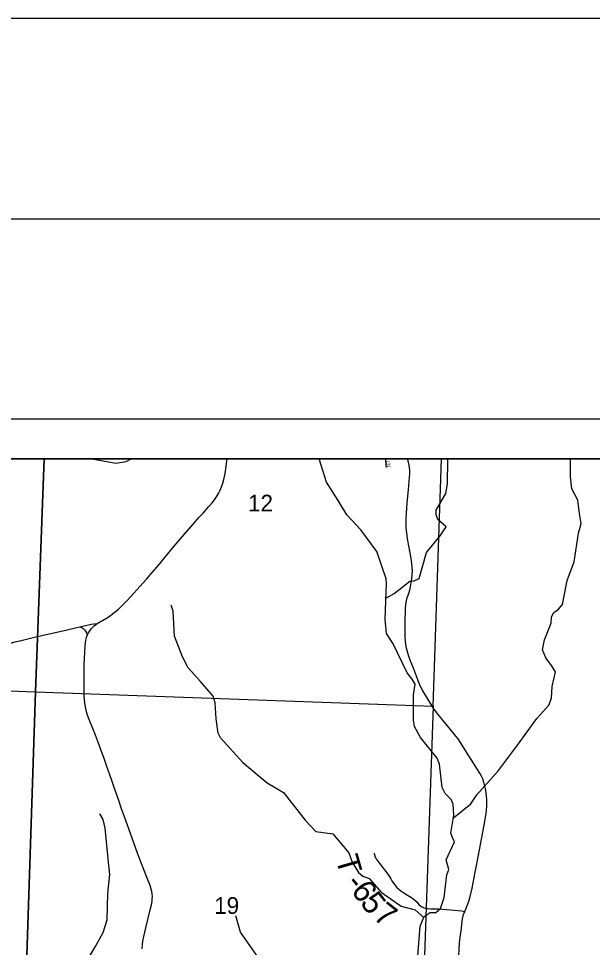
# Model space of a CAD drawing. Extents: x 0 to 34, y 0 to 22.
# Drawn here: x 26.701 to 28.135, y 19.68 to 22 of the extents above; entities that cross this region are included whole.
import ezdxf

# ---------------------------------------------------------------- set-up
doc = ezdxf.new("R2010")
doc.units = 0
for name, color, linetype in [('GM_X_Adjacent_County', 7, 'Continuous'), ('GM_X_County', 7, 'Continuous'), ('GM_X_County_Road', 7, 'Continuous'), ('GM_X_Minor_River', 7, 'Continuous'), ('GM_X_Section', 7, 'Continuous'), ('GM_X_Section_Text', 7, 'Continuous'), ('GM_X_State_Route', 7, 'Continuous'), ('GM_X_Township', 7, 'Continuous'), ('GM_X_Township_Road', 7, 'Continuous'), ('GM_X_Township_Road_Text', 7, 'Continuous'), ('GM_X_Township_Subdivision', 7, 'Continuous'), ('GM_X_Township_Subdivision_Text', 7, 'Continuous'), ('SH_Border', 7, 'Continuous'), ('SH_Cut_Line', 7, 'Continuous'), ('SH_Data', 7, 'Continuous')]:
    doc.layers.add(name, color=color, linetype=linetype)

msp = doc.modelspace()

# ---------------------------------------------------------------- linework, layer by layer
at = {"layer": 'GM_X_Adjacent_County'}
msp.add_lwpolyline([(28.7526, 20.9), (24.0167, 20.9), (24.0167, 14.1), (28.5181, 14.1)], dxfattribs=at)
at = {"layer": 'GM_X_County'}
msp.add_lwpolyline([(28.7526, 20.9), (24.0167, 20.9), (24.0167, 14.1), (28.5181, 14.1)], dxfattribs=at)
at = {"layer": 'GM_X_County_Road'}
for points in [[(27.8159, 19.7694), (27.8228, 19.7858), (27.8267, 19.7976), (27.8292, 19.8065), (27.8341, 19.8277), (27.842, 19.8673), (27.8471, 19.8926), (27.8647, 19.9854), (27.8693, 20.014), (27.8703, 20.0215), (27.8711, 20.0331), (27.8713, 20.0416), (27.8714, 20.0488), (27.8706, 20.0571), (27.8682, 20.0725), (27.8655, 20.0855), (27.8636, 20.0927), (27.8609, 20.1008), (27.8577, 20.1076), (27.8536, 20.1149), (27.8463, 20.1269), (27.8379, 20.1399), (27.8258, 20.158), (27.7991, 20.2006), (27.794, 20.2074), (27.788, 20.2148), (27.7495, 20.2613), (27.7387, 20.2759), (27.7336, 20.2842), (27.7247, 20.2988), (27.7177, 20.3101), (27.7101, 20.322), (27.7061, 20.3295), (27.7026, 20.3374), (27.6996, 20.3452), (27.6954, 20.3569), (27.6875, 20.3772), (27.6796, 20.3974), (27.6745, 20.4121), (27.6719, 20.421), (27.6705, 20.427), (27.6689, 20.4362), (27.6678, 20.4455), (27.6672, 20.4548), (27.667, 20.4703), (27.6671, 20.492), (27.6679, 20.5262), (27.6686, 20.5355), (27.6695, 20.5416), (27.6715, 20.5507), (27.6742, 20.5596), (27.6788, 20.572), (27.6807, 20.5803), (27.6824, 20.5901), (27.6837, 20.6003), (27.6848, 20.6111), (27.6851, 20.6205), (27.6848, 20.6297), (27.6839, 20.639), (27.682, 20.6513), (27.677, 20.6787), (27.6732, 20.7), (27.6709, 20.7153), (27.6697, 20.7277), (27.6692, 20.737), (27.6692, 20.7431), (27.6694, 20.7493), (27.6702, 20.7648), (27.6724, 20.7894), (27.6755, 20.8233), (27.6791, 20.8632), (27.6788, 20.8721), (27.6772, 20.884), (27.6745, 20.8948), (27.6732, 20.9)], [(26.5789, 20.4155), (26.5932, 20.4188), (26.6296, 20.4271), (26.6717, 20.4376), (26.6929, 20.4428), (26.711, 20.4472), (26.7411, 20.4544), (26.7593, 20.4586), (26.8229, 20.4731), (26.8471, 20.4786), (26.8546, 20.4804)], [(26.8546, 20.4804), (26.8682, 20.4835), (26.883, 20.4869), (26.8901, 20.4882), (26.8977, 20.4888)], [(26.8546, 20.4804), (26.8577, 20.4793), (26.8604, 20.4778), (26.8626, 20.4763), (26.8644, 20.4749), (26.8664, 20.473), (26.8687, 20.4698), (26.8707, 20.4659), (26.8727, 20.4587)], [(27.8003, 19.6426), (27.8026, 19.6909), (27.8045, 19.7047), (27.808, 19.727), (27.8088, 19.7389), (27.8107, 19.751), (27.8132, 19.7616), (27.8159, 19.7694)]]:
    msp.add_lwpolyline(points, dxfattribs=at)
at = {"layer": 'GM_X_Minor_River'}
for points in [[(26.8844, 20.9), (26.885, 20.8998), (26.9445, 20.8896), (26.9703, 20.8935), (26.9827, 20.9)], [(27.7597, 20.0795), (27.753, 20.1378), (27.7472, 20.1522), (27.705, 20.204), (27.6904, 20.2312), (27.6875, 20.2478), (27.688, 20.3108), (27.6923, 20.3373), (27.6849, 20.3498), (27.6723, 20.3656), (27.6367, 20.438), (27.6202, 20.4636), (27.6168, 20.4999), (27.6203, 20.5891), (27.6198, 20.6004), (27.5964, 20.6688), (27.5565, 20.7226), (27.5213, 20.7605), (27.5001, 20.7959), (27.4705, 20.8423), (27.4522, 20.9)], [(27.6189, 20.552), (27.6395, 20.5635), (27.6789, 20.595), (27.6899, 20.5955), (27.7019, 20.6013), (27.7205, 20.666), (27.7549, 20.7081), (27.7698, 20.7306), (27.7488, 20.7486), (27.7449, 20.7599), (27.7447, 20.7717), (27.7685, 20.8133), (27.7732, 20.8379), (27.774, 20.8982), (27.7744, 20.9)], [(27.7877, 20.0034), (27.8312, 20.0386), (27.8465, 20.0611), (27.9003, 20.122), (27.9477, 20.1847), (27.9958, 20.2515), (28.0257, 20.2852), (28.0327, 20.302), (28.0343, 20.3312), (28.0422, 20.368), (28.033, 20.3839), (28.0188, 20.4034), (28.0102, 20.4231), (28.0149, 20.4481), (28.0318, 20.49), (28.0328, 20.5056), (28.0384, 20.5166), (28.05, 20.5243), (28.0601, 20.5362), (28.0701, 20.5883), (28.0723, 20.5989), (28.0892, 20.6427), (28.1002, 20.7148), (28.1071, 20.7384), (28.1023, 20.7638), (28.0982, 20.7971), (28.0835, 20.8254), (28.0798, 20.8549), (28.0804, 20.9)], [(27.2617, 20.1419), (27.2061, 20.2034), (27.2003, 20.2147), (27.1948, 20.2503), (27.1927, 20.2909), (27.1873, 20.3072), (27.156, 20.3438), (27.1247, 20.3785), (27.1109, 20.4057), (27.091, 20.4576), (27.0872, 20.5194), (27.0829, 20.5345)], [(27.2617, 20.1419), (27.3226, 20.0907), (27.363, 20.0665), (27.4171, 19.9973), (27.4439, 19.9696), (27.4863, 19.9636), (27.5265, 19.9162), (27.5343, 19.8928), (27.5505, 19.8672), (27.5612, 19.8575), (27.5768, 19.8516), (27.607, 19.8174), (27.6569, 19.7827), (27.6918, 19.7736), (27.7138, 19.7548)], [(27.6991, 19.6576), (27.7044, 19.7331), (27.7147, 19.7568), (27.7293, 19.7671), (27.7433, 19.7673), (27.755, 19.7765), (27.7641, 19.8043), (27.7711, 19.8612), (27.7759, 19.8746), (27.7699, 19.8988), (27.7899, 19.9433), (27.7852, 19.9543), (27.7813, 19.9649), (27.7888, 20.0101), (27.7866, 20.0377), (27.7816, 20.049), (27.767, 20.0644), (27.7597, 20.0795)], [(26.7483, 19.5359), (26.7793, 19.5451), (26.8087, 19.5624), (26.849, 19.6062), (26.8941, 19.6835), (26.9124, 19.7169), (26.9225, 19.7489), (26.924, 19.8141), (26.9291, 19.8619), (26.9254, 19.9006), (26.9174, 19.9779), (26.9124, 19.9991), (26.904, 20.0135)], [(27.302, 19.6509), (27.2557, 19.7178), (27.2438, 19.7587)]]:
    msp.add_lwpolyline(points, dxfattribs=at)
at = {"layer": 'GM_X_Section'}
for p, q in [((26.7655, 20.9), (25.7754, 20.9)), ((27.7581, 20.9), (26.7655, 20.9))]:
    msp.add_line(p, q, dxfattribs=at)
for points in [[(25.7754, 20.9), (25.7533, 20.3558), (26.7437, 20.3179), (26.7655, 20.9)], [(26.7655, 20.9), (26.7437, 20.3179), (27.7374, 20.2821), (27.7581, 20.9)]]:
    msp.add_lwpolyline(points, dxfattribs=at)
for points in [[(25.7533, 20.3558), (26.7437, 20.3179), (26.7101, 19.3051), (25.7174, 19.3453)], [(26.7437, 20.3179), (27.7374, 20.2821), (27.7021, 19.2764), (26.7101, 19.3051)]]:
    msp.add_lwpolyline(points, close=True, dxfattribs=at)
at = {"layer": 'GM_X_State_Route'}
msp.add_lwpolyline([(27.0102, 19.6764), (27.0109, 19.6857), (27.0122, 19.695), (27.0145, 19.7072), (27.0194, 19.7285), (27.0252, 19.7526), (27.0304, 19.7738), (27.0331, 19.7858), (27.0347, 19.7949), (27.0354, 19.801), (27.0356, 19.8072), (27.0353, 19.8133), (27.0343, 19.8193), (27.0328, 19.8252), (27.0298, 19.834), (27.0207, 19.8571), (27.0151, 19.8716), (27.0051, 19.8976), (27.0017, 19.9063), (26.9974, 19.9179), (26.9901, 19.9383), (26.9807, 19.9646), (26.9662, 20.0056), (26.9587, 20.026), (26.9516, 20.0465), (26.9404, 20.0788), (26.9333, 20.0993), (26.9211, 20.1345), (26.9158, 20.149), (26.9054, 20.1782), (26.9011, 20.1899), (26.8935, 20.2102), (26.8855, 20.2304), (26.8794, 20.2447), (26.8761, 20.2534), (26.8731, 20.2622), (26.8705, 20.2712), (26.8684, 20.2804), (26.8668, 20.2896), (26.8658, 20.2989), (26.8654, 20.3083), (26.8652, 20.3269), (26.8655, 20.3518), (26.8655, 20.3641), (26.8656, 20.3857), (26.866, 20.4011), (26.8665, 20.4166), (26.8676, 20.4321), (26.8686, 20.4414), (26.8696, 20.4476), (26.871, 20.4537), (26.8719, 20.4567), (26.8727, 20.4587), (26.8735, 20.4605), (26.8758, 20.4653), (26.8791, 20.4706), (26.881, 20.4731), (26.883, 20.4755), (26.8852, 20.4778), (26.8864, 20.4789), (26.8905, 20.4828), (26.8977, 20.4888), (26.9074, 20.4944), (26.9107, 20.4964), (26.9207, 20.5021), (26.9298, 20.508), (26.9362, 20.513), (26.9436, 20.5188), (26.9507, 20.5249), (26.9621, 20.5355), (26.9729, 20.5466), (26.9897, 20.5649), (27.0043, 20.581), (27.0207, 20.5997), (27.035, 20.6161), (27.0531, 20.6374), (27.0631, 20.6493), (27.0847, 20.6758), (27.1149, 20.7112), (27.1373, 20.737), (27.1517, 20.7533), (27.1621, 20.7648), (27.1765, 20.781), (27.1846, 20.7904), (27.1904, 20.7978), (27.1958, 20.8054), (27.2006, 20.8135), (27.2049, 20.8218), (27.2085, 20.8305), (27.2115, 20.8394), (27.2139, 20.8484), (27.2172, 20.8637), (27.2202, 20.8821), (27.2225, 20.9)], dxfattribs=at)
at = {"layer": 'GM_X_Township'}
msp.add_lwpolyline([(28.7526, 20.9), (24.0167, 20.9), (24.0167, 18.4402)], dxfattribs=at)
at = {"layer": 'GM_X_Township_Road'}
msp.add_lwpolyline([(27.5895, 19.9148), (27.5917, 19.9075), (27.5925, 19.9052), (27.5937, 19.9028), (27.5955, 19.8996), (27.5985, 19.8955), (27.6039, 19.8881), (27.6122, 19.8775), (27.6187, 19.8692), (27.6255, 19.8602), (27.629, 19.8551), (27.6315, 19.8509), (27.6341, 19.8462), (27.6374, 19.8409), (27.6419, 19.8352), (27.6457, 19.8305), (27.6509, 19.8248), (27.6561, 19.821), (27.6635, 19.816), (27.6727, 19.8106), (27.6829, 19.8044), (27.69, 19.7989), (27.6967, 19.7928), (27.7016, 19.7871), (27.7064, 19.7831), (27.709, 19.7814), (27.7117, 19.7798), (27.7146, 19.7786), (27.7176, 19.7778), (27.7206, 19.7772), (27.7237, 19.7769), (27.7306, 19.7764), (27.7396, 19.7759), (27.7505, 19.7757), (27.7708, 19.7745), (27.7897, 19.7729), (27.7997, 19.7721), (27.808, 19.771), (27.8159, 19.7694)], dxfattribs=at)
at = {"layer": 'GM_X_Township_Subdivision'}
msp.add_lwpolyline([(27.6183, 20.9), (27.6183, 20.8946), (27.6185, 20.8881), (27.6189, 20.8833), (27.6197, 20.8786)], dxfattribs=at)
at = {"layer": 'SH_Border'}
msp.add_lwpolyline([(2, 21.5), (33.5, 21.5), (33.5, 0.5), (2, 0.5)], close=True, dxfattribs=at)
at = {"layer": 'SH_Cut_Line'}
msp.add_lwpolyline([(0, 0), (34, 0), (34, 22), (0, 22)], close=True, dxfattribs=at)
at = {"layer": 'SH_Data'}
for points in [[(23.9167, 21), (30.9167, 21), (30.9167, 14), (23.9167, 14)], [(24.0167, 20.9), (30.8167, 20.9), (30.8167, 14.1), (24.0167, 14.1)]]:
    msp.add_lwpolyline(points, close=True, dxfattribs=at)

# ---------------------------------------------------------------- texts
at = {"layer": 'GM_X_Section_Text'}
for s, p in [('12', (27.2747, 20.7687)), ('19', (27.1901, 19.7634))]:
    msp.add_text(s, height=0.04186, rotation=0, dxfattribs=at).set_placement(p)
at = {"layer": 'GM_X_Township_Road_Text'}
for s, rotation, p in [('T', 286.1738, (27.493, 19.9016)), ('-', 309.2274, (27.5164, 19.8388)), ('6', 305.2231, (27.5305, 19.8216)), ('5', 308.1311, (27.5526, 19.7905)), ('7', 321.828, (27.5846, 19.7525))]:
    msp.add_text(s, height=0.0568, rotation=rotation, dxfattribs=at).set_placement(p)
at = {"layer": 'GM_X_Township_Subdivision_Text'}
for s, rotation, p in [('L', 273.5428, (27.6204, 20.8957)), ('N', 279.063, (27.6209, 20.8881))]:
    msp.add_text(s, height=0.00947, rotation=rotation, dxfattribs=at).set_placement(p)

doc.saveas('drawing.dxf')
